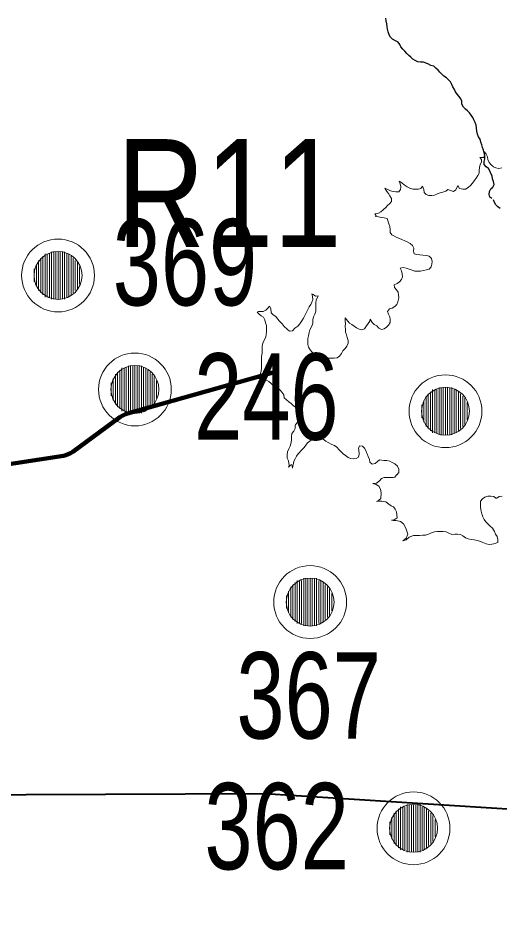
# Model space of a CAD drawing. Extents: x 553962 to 842807, y 8883888 to 9032388.
# Drawn here: x 703268 to 705500, y 8960962 to 8965153 of the extents above; entities that cross this region are included whole.
import ezdxf
from ezdxf.enums import TextEntityAlignment as Align

# ---------------------------------------------------------------- set-up
doc = ezdxf.new("R2010")
doc.units = 0
doc.header["$LTSCALE"] = 160
for name, color, linetype, lineweight in [('15', 7, 'Continuous', 25), ('21', 7, 'Continuous', 25), ('32', 7, 'Continuous', 13), ('33', 7, 'Continuous', 13), ('7', 7, 'Continuous', 90), ('8', 7, 'Continuous', 13)]:
    doc.layers.add(name, color=color, linetype=linetype, lineweight=lineweight)

msp = doc.modelspace()

# ---------------------------------------------------------------- linework, layer by layer
at = {"layer": '15', "lineweight": 40}
for points in [[(693487.4, 8962819.8), (696836.9, 8961144.8), (697384.1, 8960961.8), (697603.7, 8960973.6), (697714.4, 8961082.3), (698321.2, 8961447.4), (698679, 8961567.8), (700187.3, 8961472.5), (701093.5, 8961547), (704410.2, 8961560.7)], [(704410.2, 8961560.7), (707197.4, 8961384.6), (708568.6, 8961290.5), (709350.1, 8961228.9), (709812.8, 8961324.8)]]:
    msp.add_lwpolyline(points, dxfattribs=at)
at = {"layer": '21'}
for points in [[(705462, 8964317), (705454, 8964323.8), (705449.7, 8964336.7), (705451.5, 8964350), (705458.7, 8964361.9), (705468.1, 8964370.6), (705473.4, 8964382.4), (705470.6, 8964396.2), (705466.6, 8964409.2), (705463.8, 8964422), (705458.7, 8964433.7), (705454.1, 8964445.5), (705446.7, 8964456.5), (705436.3, 8964463.7), (705427.9, 8964475.5), (705427.5, 8964488.9), (705430.3, 8964502), (705430.9, 8964516), (705426.8, 8964529), (705424.1, 8964541.7), (705419.9, 8964553.7), (705415.7, 8964565.5), (705411.4, 8964578.6), (705408.1, 8964592.5), (705401.5, 8964603.7), (705395.9, 8964616.2), (705392.6, 8964629.3), (705391.6, 8964643), (705390.5, 8964656.5), (705385.8, 8964668.8), (705380.1, 8964681.2), (705374, 8964692.3), (705367.4, 8964703.5), (705359.7, 8964714.5), (705350.4, 8964723.6), (705340.7, 8964731.8), (705331.4, 8964740.9), (705324.3, 8964754.5), (705324.1, 8964767.8), (705318.9, 8964779.2), (705311.5, 8964790.4), (705302.1, 8964801.5), (705294.8, 8964811.6), (705289.5, 8964823), (705282.6, 8964834.3), (705277.5, 8964846), (705270.7, 8964857.2), (705262.2, 8964867.1), (705252.3, 8964876.4), (705240.9, 8964883.8), (705231.1, 8964892.9), (705222.1, 8964902.5), (705213.5, 8964912.7), (705203.7, 8964921.9), (705193.6, 8964930.3), (705180.4, 8964933.5), (705169.9, 8964940.5), (705158.2, 8964945), (705145.8, 8964948.7), (705132.4, 8964948.5), (705119.9, 8964950.6), (705108.2, 8964956.4), (705096.8, 8964963.6), (705087, 8964971.5), (705077.6, 8964979.9), (705068.8, 8964989.5), (705059.7, 8964999.7), (705050, 8965008.9), (705041.6, 8965019.5), (705036.2, 8965031.3), (705028.3, 8965041.6), (705016.9, 8965048.5), (705002.3, 8965055.8), (704992.8, 8965064.7), (704987, 8965075.9), (704982.4, 8965089.2), (704979.4, 8965101.5), (704977.2, 8965114.3), (704976.5, 8965127.2), (704973.7, 8965140.4), (704971.5, 8965153.2)], [(705501.2, 8964271.4), (705490.1, 8964278.3), (705480.6, 8964288), (705474.5, 8964299), (705470.1, 8964311.2)]]:
    msp.add_lwpolyline(points, dxfattribs=at)
at = {"layer": '32'}
for p, q in [((704591, 8962558), (704591, 8962338)), ((704601, 8962558), (704601, 8962338)), ((704611, 8962558), (704611, 8962338)), ((704621, 8962558), (704621, 8962338)), ((704631, 8962558), (704631, 8962338)), ((704641, 8962558), (704641, 8962338)), ((704651, 8962558), (704651, 8962338)), ((704531, 8962518), (704531, 8962378)), ((704541, 8962528), (704541, 8962368)), ((704551, 8962538), (704551, 8962358)), ((704561, 8962548), (704561, 8962348)), ((704571, 8962548), (704571, 8962348)), ((704581, 8962548), (704581, 8962348)), ((704661, 8962548), (704661, 8962348)), ((704671, 8962548), (704671, 8962348)), ((704681, 8962538), (704681, 8962358)), ((704691, 8962528), (704691, 8962368)), ((704701, 8962518), (704701, 8962378)), ((704511, 8962478), (704511, 8962418)), ((704521, 8962498), (704521, 8962398)), ((704711, 8962508), (704711, 8962388)), ((704721, 8962488), (704721, 8962408))]:
    msp.add_line(p, q, dxfattribs=at)
for radius in [168.7, 111]:
    msp.add_circle((704621, 8962448), radius, dxfattribs=at)
at = {"layer": '33'}
for p, q in [((703423, 8964071), (703423, 8963851)), ((703433, 8964071), (703433, 8963851)), ((703443, 8964071), (703443, 8963851)), ((703453, 8964071), (703453, 8963851)), ((703463, 8964071), (703463, 8963851)), ((703473, 8964071), (703473, 8963851)), ((703483, 8964071), (703483, 8963851)), ((703363, 8964031), (703363, 8963891)), ((703373, 8964041), (703373, 8963881)), ((703383, 8964051), (703383, 8963871)), ((703393, 8964061), (703393, 8963861)), ((703403, 8964061), (703403, 8963861)), ((703413, 8964061), (703413, 8963861)), ((703493, 8964061), (703493, 8963861)), ((703503, 8964061), (703503, 8963861)), ((703513, 8964051), (703513, 8963871)), ((703523, 8964041), (703523, 8963881)), ((703533, 8964031), (703533, 8963891)), ((703343, 8963991), (703343, 8963931)), ((703353, 8964011), (703353, 8963911)), ((703543, 8964021), (703543, 8963901)), ((703553, 8964001), (703553, 8963921)), ((703739, 8963523), (703739, 8963343)), ((703749, 8963533), (703749, 8963333)), ((703759, 8963533), (703759, 8963333)), ((703769, 8963533), (703769, 8963333)), ((703779, 8963543), (703779, 8963323)), ((703789, 8963543), (703789, 8963323)), ((703799, 8963543), (703799, 8963323)), ((703809, 8963543), (703809, 8963323)), ((703819, 8963543), (703819, 8963323)), ((703829, 8963543), (703829, 8963323)), ((703839, 8963543), (703839, 8963323)), ((703849, 8963533), (703849, 8963333)), ((703859, 8963533), (703859, 8963333)), ((703869, 8963523), (703869, 8963343)), ((703709, 8963483), (703709, 8963383)), ((703719, 8963503), (703719, 8963363)), ((703729, 8963513), (703729, 8963353)), ((703879, 8963513), (703879, 8963353)), ((703889, 8963503), (703889, 8963363)), ((703899, 8963493), (703899, 8963373)), ((703699, 8963463), (703699, 8963403)), ((703909, 8963473), (703909, 8963393)), ((705218, 8963442), (705218, 8963222)), ((705228, 8963442), (705228, 8963222)), ((705238, 8963442), (705238, 8963222)), ((705248, 8963442), (705248, 8963222)), ((705258, 8963442), (705258, 8963222)), ((705268, 8963442), (705268, 8963222)), ((705278, 8963442), (705278, 8963222)), ((705158, 8963402), (705158, 8963262)), ((705168, 8963412), (705168, 8963252)), ((705178, 8963422), (705178, 8963242)), ((705188, 8963432), (705188, 8963232)), ((705198, 8963432), (705198, 8963232)), ((705208, 8963432), (705208, 8963232)), ((705288, 8963432), (705288, 8963232)), ((705298, 8963432), (705298, 8963232)), ((705308, 8963422), (705308, 8963242)), ((705318, 8963412), (705318, 8963252)), ((705328, 8963402), (705328, 8963262)), ((705138, 8963362), (705138, 8963302)), ((705148, 8963382), (705148, 8963282)), ((705338, 8963392), (705338, 8963272)), ((705348, 8963372), (705348, 8963292)), ((705070, 8961510), (705070, 8961290)), ((705080, 8961510), (705080, 8961290)), ((705090, 8961510), (705090, 8961290)), ((705100, 8961510), (705100, 8961290)), ((705110, 8961510), (705110, 8961290)), ((705120, 8961510), (705120, 8961290)), ((705130, 8961510), (705130, 8961290)), ((705010, 8961470), (705010, 8961330)), ((705020, 8961480), (705020, 8961320)), ((705030, 8961490), (705030, 8961310)), ((705040, 8961500), (705040, 8961300)), ((705050, 8961500), (705050, 8961300)), ((705060, 8961500), (705060, 8961300)), ((705140, 8961500), (705140, 8961300)), ((705150, 8961500), (705150, 8961300)), ((705160, 8961490), (705160, 8961310)), ((705170, 8961480), (705170, 8961320)), ((705180, 8961470), (705180, 8961330)), ((704990, 8961430), (704990, 8961370)), ((705000, 8961450), (705000, 8961350)), ((705190, 8961460), (705190, 8961340)), ((705200, 8961440), (705200, 8961360))]:
    msp.add_line(p, q, dxfattribs=at)
for centre, radius in [((703453, 8963961), 168.7), ((703453, 8963961), 111), ((703809, 8963433), 168.7), ((703809, 8963433), 111), ((705248, 8963332), 168.7), ((705248, 8963332), 111), ((705100, 8961400), 168.7), ((705100, 8961400), 111)]:
    msp.add_circle(centre, radius, dxfattribs=at)
at = {"layer": '7'}
for p, q in [((703774.5, 8963321.1), (704450.1, 8963511.6)), ((703521.2, 8963144.3), (703739.1, 8963303.9)), ((702352.6, 8962950.9), (703477.5, 8963126.2))]:
    msp.add_line(p, q, dxfattribs=at)
for centre, radius, start, end in [((703804.6, 8963214.4), 110.9, 105.7483, 126.2005), ((703462.1, 8963225), 100, 278.8567, 306.2005)]:
    msp.add_arc(centre, radius, start, end, dxfattribs=at)
at = {"layer": '8'}
for points in [[(705508.8, 8964459.2), (705495.1, 8964456.2), (705481.5, 8964459), (705469.8, 8964463.8), (705459.6, 8964472.8), (705450.8, 8964483.8), (705443.8, 8964497.4), (705442.1, 8964510.8), (705436.4, 8964522.5), (705429, 8964534), (705429, 8964531.9), (705429.2, 8964519.4), (705426.1, 8964507.2), (705423.2, 8964507.2), (705407.6, 8964507), (705414.2, 8964498.4), (705414.8, 8964485.9), (705409.3, 8964474.3), (705406.3, 8964461.3), (705404.8, 8964447.5), (705403.3, 8964434.9), (705397.3, 8964423.4), (705389.6, 8964411.7), (705380.8, 8964399.9), (705372.4, 8964388.6), (705364.1, 8964378), (705353.2, 8964368.1), (705340.6, 8964361.4), (705328.1, 8964360.7), (705313.5, 8964363.1), (705304.7, 8964377.1), (705295.7, 8964357.2), (705285, 8964350.4), (705271.7, 8964354.4), (705259.5, 8964358.6), (705248.9, 8964350.9), (705236.2, 8964346.2), (705223.8, 8964344.1), (705210.5, 8964338.9), (705197.8, 8964333.5), (705184.1, 8964331.1), (705170.6, 8964331.1), (705158.7, 8964335.5), (705148.8, 8964345.9), (705147.6, 8964359.1), (705142.2, 8964375.2), (705134.4, 8964364), (705122.3, 8964360.5), (705109.8, 8964360.3), (705096.1, 8964360.6), (705083.1, 8964364.8), (705070.5, 8964371.5), (705056.1, 8964381.1), (705046.3, 8964390), (705032.8, 8964398.1), (705038.2, 8964385.6), (705040.4, 8964372.3), (705039.4, 8964359.2), (705031.3, 8964348.2), (705018.2, 8964347.9), (705005.3, 8964349.2), (704993, 8964352.8), (704981, 8964359.8), (704966.4, 8964365.4), (704975.5, 8964350.4), (704983.3, 8964339.9), (704989.9, 8964329.2), (704997.2, 8964316.8), (704998.6, 8964303.4), (704989.9, 8964294.4), (704980, 8964285.8), (704971, 8964275.2), (704959.3, 8964264.4), (704948, 8964255.5), (704935, 8964248.2), (704920.2, 8964245.9), (704927.3, 8964238.4), (704923, 8964234.7), (704937.8, 8964232.3), (704950.2, 8964229.7), (704963.8, 8964227.3), (704978.5, 8964225)], [(704978.5, 8964225), (704985.5, 8964200.1), (704990.3, 8964187.7), (704991, 8964174.3), (704992.1, 8964160.3), (704999.3, 8964149.8), (705012, 8964143.6), (705023, 8964137.5), (705034.6, 8964131.7), (705046.5, 8964127), (705059.2, 8964121.8), (705071.1, 8964116.7), (705084.1, 8964109.2), (705094.8, 8964100.2), (705100.7, 8964087.1), (705100.1, 8964074.3), (705103.2, 8964061.2), (705115.4, 8964057.7), (705128.8, 8964057), (705142.5, 8964055.7), (705159.4, 8964053.6), (705173.1, 8964049.6), (705182.5, 8964040.3), (705185.9, 8964026.1), (705185.5, 8964013.3), (705181.2, 8964000.2), (705172.8, 8963990.1), (705160.1, 8963986.8), (705146.9, 8963983.5), (705132.4, 8963980.7), (705119.5, 8963980.3), (705106.3, 8963980.9), (705093, 8963985), (705080.2, 8963990), (705066.3, 8963994.4), (705051.2, 8963998.1), (705038, 8963994.2), (705043.8, 8963982.2), (705047, 8963969.2), (705048.3, 8963955.1), (705044.2, 8963942.1), (705034.5, 8963931.2), (705023.5, 8963923.6), (705010.3, 8963917.2), (705011.1, 8963904.7), (705020.7, 8963893.8), (705028.1, 8963882.9), (705031, 8963870.6), (705031.2, 8963857.7), (705027.7, 8963838.5), (705022, 8963826.8), (705013, 8963817.5), (705001.4, 8963810.2), (704988.7, 8963805.9), (704980, 8963794.6), (704984.5, 8963781.9), (704990.2, 8963770), (704992, 8963756.5), (704991.3, 8963743.4), (704984.4, 8963730.8), (704974.1, 8963721.1), (704964.2, 8963713.1), (704951.3, 8963710.7), (704939.2, 8963716.1), (704929.2, 8963727.1)], [(704663.2, 8963585), (704649.8, 8963591.1), (704638.9, 8963598.7), (704628.4, 8963606.8), (704620.6, 8963616.8), (704613.2, 8963628.3), (704610.2, 8963640.6), (704610.1, 8963656.1), (704611, 8963669), (704612.9, 8963681.6), (704615.8, 8963696.2), (704620, 8963708.7), (704629.5, 8963726.3), (704633.5, 8963740.4), (704633.9, 8963755.5), (704636.5, 8963769.9), (704642.5, 8963781), (704647.5, 8963794.9), (704647.8, 8963807.6), (704647.8, 8963821.3), (704647.8, 8963834), (704649.3, 8963846.5), (704657.6, 8963866.4), (704645.4, 8963865.4), (704634.8, 8963872.2), (704628, 8963876.3), (704631.1, 8963863.5), (704634, 8963850.4), (704629.5, 8963837.9), (704623.4, 8963826.5), (704616.1, 8963816), (704609.9, 8963803.8), (704603.9, 8963791.5), (704597.5, 8963778.1), (704589.5, 8963763.3), (704582.9, 8963750.3), (704572.5, 8963737.1), (704563.9, 8963726.3), (704550.3, 8963716.1), (704539.4, 8963704.5), (704525.1, 8963703.6), (704513.9, 8963711.6), (704501.2, 8963724.9), (704490.7, 8963736.6), (704478.3, 8963748.5), (704469.9, 8963760.5), (704461.8, 8963771.6), (704450.1, 8963778.8), (704441, 8963787.9), (704438.7, 8963808.2), (704432.3, 8963819.5), (704424.2, 8963809.5), (704415.3, 8963799.6), (704403.7, 8963794.5), (704390, 8963794.5), (704382.2, 8963793.3), (704375.9, 8963790.8), (704384.2, 8963782.4), (704394, 8963774), (704404.9, 8963767.8), (704410.6, 8963755.5), (704413.5, 8963741.3), (704418.8, 8963728.9), (704418.8, 8963715.5), (704418.7, 8963700.6)], [(704929.2, 8963727.1), (704917.6, 8963734.4), (704908.6, 8963743.4), (704899.7, 8963758.5), (704897.1, 8963749.6), (704889.6, 8963738), (704882.8, 8963727.1), (704873.4, 8963713.8), (704860.6, 8963709.3), (704848.2, 8963712.1), (704835.1, 8963717.7), (704824.9, 8963725.6), (704814.5, 8963733.2), (704804, 8963740.1), (704795.1, 8963749), (704783, 8963764.1), (704783, 8963749.8), (704785.2, 8963737.8), (704783.8, 8963724.9), (704784, 8963712.2), (704784.8, 8963698.6), (704789.3, 8963685.5), (704792.9, 8963673), (704797.8, 8963660.2), (704797.7, 8963646.7), (704791.5, 8963633.2), (704783.2, 8963623), (704773, 8963611.4), (704766, 8963600.1), (704756.8, 8963587.3), (704745.9, 8963579.3), (704731.8, 8963578.1), (704718.5, 8963578.1), (704706, 8963578.1), (704690.9, 8963578.1), (704675.9, 8963579.7), (704663.2, 8963585)], [(704418.7, 8963700.6), (704417.7, 8963687.6), (704414.9, 8963675), (704409.7, 8963663.6), (704401.8, 8963647.8), (704399.3, 8963632.8), (704399.4, 8963614.8), (704398, 8963600.8), (704394.8, 8963586), (704394.8, 8963572.3), (704394.9, 8963559.4), (704394.9, 8963545.2), (704394.9, 8963530.8), (704393.7, 8963517.7), (704388.9, 8963502.5), (704385.1, 8963483.9)], [(704385.1, 8963483.9), (704392.2, 8963478.3), (704405, 8963475.8), (704418.1, 8963475.9)], [(704418.1, 8963475.9), (704429.7, 8963470.4), (704438.5, 8963461.4), (704448.3, 8963452.1), (704460.8, 8963445), (704472.1, 8963438.6), (704481.6, 8963430.2), (704489.7, 8963419.7), (704498.5, 8963408.6), (704501.1, 8963394.8), (704511.5, 8963384.6), (704522.9, 8963375.6), (704532.7, 8963367.3), (704542.8, 8963359.1), (704552.8, 8963350.6), (704559.7, 8963338.4), (704566.6, 8963326.5), (704570.9, 8963313.5), (704571.7, 8963293.7), (704564.9, 8963284.8)], [(704553.2, 8963268.3), (704552, 8963266.5), (704551.7, 8963251.6), (704544.6, 8963240.3), (704536.1, 8963228.8), (704535.1, 8963215.3), (704535.1, 8963201.3), (704533.1, 8963187), (704528.8, 8963170.8), (704521.8, 8963157.6), (704516.2, 8963144.2), (704516.1, 8963143.3)], [(704564.9, 8963284.8), (704562.8, 8963282), (704553.2, 8963268.3)], [(704572.7, 8963143), (704574.4, 8963145.2), (704583.4, 8963154.8), (704592.7, 8963164.3), (704601.3, 8963175.5), (704609.3, 8963185.7), (704618.8, 8963193.9), (704630.9, 8963201.2), (704642.7, 8963206.9), (704655.6, 8963208.1), (704669.7, 8963207.4), (704681.7, 8963202), (704694, 8963193.3), (704704.8, 8963187), (704721.7, 8963178.2), (704733.5, 8963172.8), (704744.5, 8963165), (704755, 8963153.6), (704764.1, 8963144.1), (704766.6, 8963141.9)], [(704516.1, 8963143.3), (704514.7, 8963129.4), (704514.4, 8963114.6), (704521.2, 8963102.2), (704524.1, 8963080), (704520.7, 8963073), (704526.7, 8963079.6), (704533.8, 8963084.9), (704538, 8963078.6), (704539.6, 8963069), (704540.6, 8963078.7), (704543.1, 8963089.5), (704545.4, 8963100.9), (704551.7, 8963112), (704558.2, 8963124), (704566.1, 8963134.5), (704572.7, 8963143)], [(704766.6, 8963141.9), (704774.6, 8963135.1), (704785, 8963127.1), (704796.9, 8963118.4), (704808.6, 8963112.4), (704821.1, 8963112.2), (704834, 8963112.8), (704844.6, 8963119.6), (704847.5, 8963132.5), (704847.3, 8963141.5)], [(704845.8, 8963154.3), (704845, 8963159.6), (704848.4, 8963169.1)], [(704847.3, 8963141.5), (704847.1, 8963146.1), (704845.8, 8963154.3)], [(704848.4, 8963169.1), (704849.5, 8963171.9), (704863.3, 8963169.9), (704872.9, 8963161.6), (704880.7, 8963146.7), (704882.4, 8963141.3)], [(704882.4, 8963141.3), (704884.6, 8963134.7), (704890, 8963121.7), (704895.4, 8963109), (704897.9, 8963096.4), (704908.1, 8963087), (704921.5, 8963090.1), (704932.6, 8963099.7), (704942.6, 8963107.2), (704962.7, 8963103.7), (704976.5, 8963103.8), (704989.6, 8963100.9), (705001.5, 8963094.9), (705013.3, 8963088.9), (705026.2, 8963077.6), (705031.2, 8963063.5), (705031.7, 8963049), (705022.2, 8963037.8), (705021.3, 8963037.6), (705013.3, 8963025.9), (705005.9, 8963025.7), (704993.4, 8963025.7), (704979, 8963025.5), (704964.2, 8963025), (704951.9, 8963020.2), (704942.8, 8963009.1), (704927.8, 8962999.2), (704912, 8962996.6), (704926.6, 8962993.4), (704938.9, 8962985), (704946.7, 8962971.8), (704950.1, 8962954.7), (704947.9, 8962927.9), (704939.2, 8962920.7), (704928.2, 8962913.9), (704939.5, 8962915.9), (704953.3, 8962915.6), (704971.1, 8962912.8), (704985.3, 8962901.2), (704996.2, 8962894.2), (705007.7, 8962889.1), (705015.3, 8962879), (705020.7, 8962865.5), (705024.7, 8962838.7), (705010.7, 8962829.6), (704998.4, 8962827.1), (705005.9, 8962825.7), (705018.9, 8962826.2), (705040, 8962821.3), (705053.4, 8962810.5), (705060.3, 8962799.2), (705065.1, 8962785.8), (705072.9, 8962762.3), (705065.5, 8962744.6), (705051.1, 8962732), (705065.1, 8962736.7), (705079, 8962749.3), (705099.2, 8962755.9), (705112.9, 8962756.8), (705127.5, 8962757), (705143.3, 8962757.2), (705156, 8962757.7), (705169.4, 8962762.5), (705182.6, 8962768.2), (705196.8, 8962773), (705209.7, 8962774.8), (705222.4, 8962775), (705237.7, 8962775.1), (705250.6, 8962773), (705263, 8962766.7), (705277.2, 8962760.6), (705290.7, 8962762.6), (705303.7, 8962762.8), (705317.3, 8962760.4), (705328.9, 8962754.6), (705340.2, 8962745.4), (705353.4, 8962740.9), (705367.3, 8962737.8), (705381, 8962735.8), (705396.2, 8962733.2), (705410, 8962728.6), (705420.3, 8962724.7)], [(705472.2, 8962718), (705476, 8962718.6), (705491, 8962723.8), (705490.8, 8962738.5), (705487.2, 8962751.2), (705479.9, 8962762.8), (705474.7, 8962774.3), (705465.9, 8962789.7), (705455.1, 8962800.4), (705444.8, 8962810.5), (705434.2, 8962819.7), (705426.8, 8962830.5), (705421.8, 8962842.5), (705417.1, 8962856.5), (705413.3, 8962868.8), (705411, 8962886.5), (705409.5, 8962900.1), (705411, 8962914.7), (705419.2, 8962926.1), (705430.4, 8962934.7), (705443.6, 8962938.5), (705458.2, 8962938.7), (705472.1, 8962937.6), (705481.8, 8962929.5), (705486.3, 8962930), (705496.5, 8962937.8), (705511, 8962938)], [(705420.3, 8962724.7), (705421.8, 8962724.1), (705436.4, 8962717.6), (705450.1, 8962715.4), (705463, 8962716.6), (705472.2, 8962718)]]:
    msp.add_lwpolyline(points, dxfattribs=at)

# ---------------------------------------------------------------- texts
at = {"layer": '32', "width": 0.75}
msp.add_text('367', height=400, dxfattribs=at).set_placement((704279.3, 8961815.8))
at = {"layer": '33', "width": 0.75}
for s, p in [('369', (703706.3, 8963822.4)), ('246', (704083.2, 8963200.1)), ('362', (704131.1, 8961210))]:
    msp.add_text(s, height=400, dxfattribs=at).set_placement(p)
at = {"layer": '8', "width": 0.85}
msp.add_text('R11', height=500, dxfattribs=at).set_placement((704245.3, 8964092.5), align=Align.CENTER)

doc.saveas('drawing.dxf')
